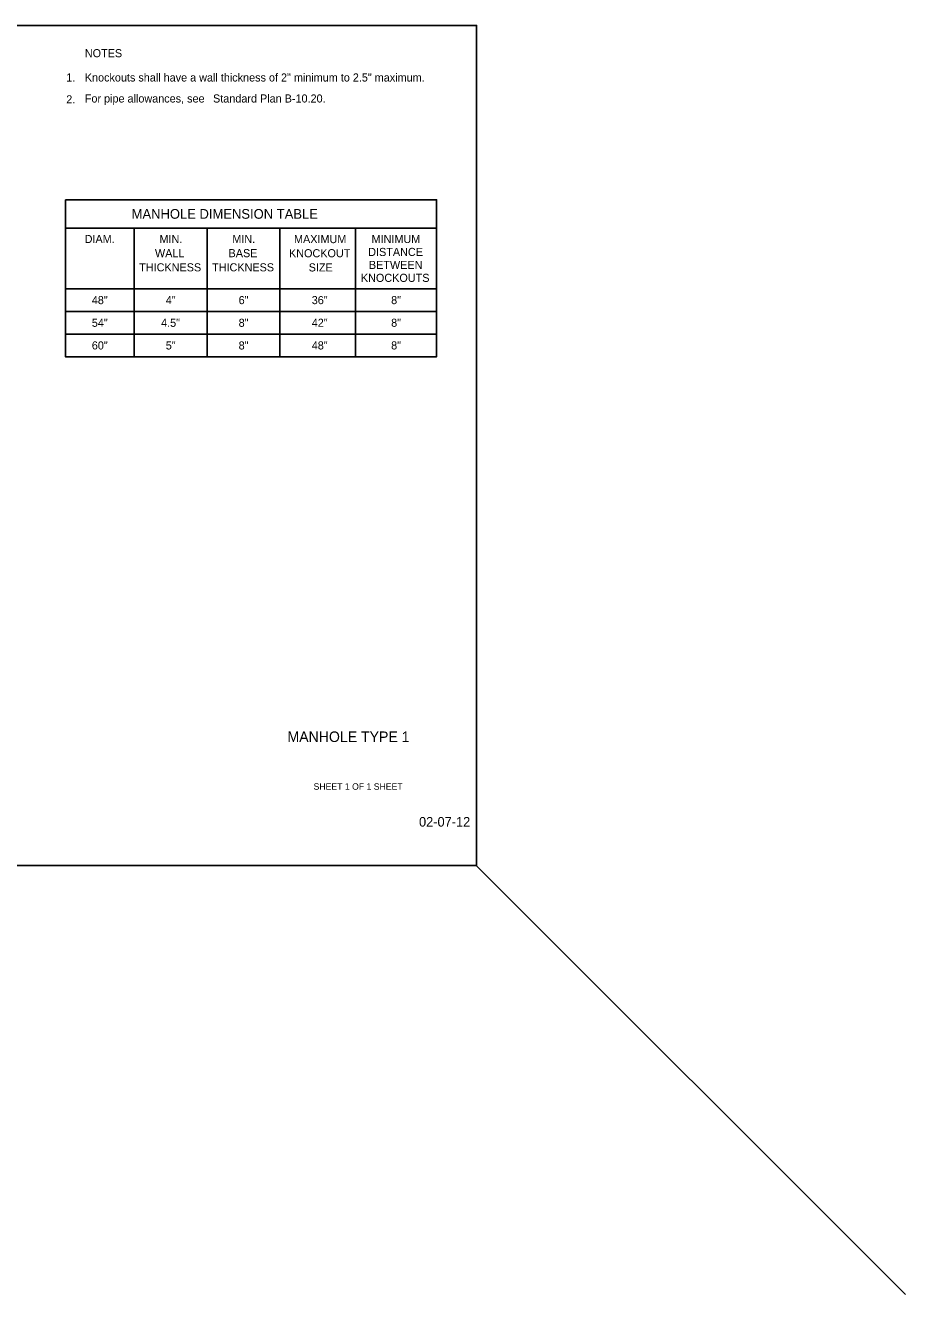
# Model space of a CAD drawing. Extents: x 99862 to 104211, y 98939 to 102076.
# Drawn here: x 102036 to 104211, y 98939 to 102076 of the extents above; entities that cross this region are included whole.
import ezdxf

# ---------------------------------------------------------------- set-up
doc = ezdxf.new("R2010")
doc.units = 0
for name, color, linetype in [('Level 1', 7, 'Continuous'), ('Level 19', 7, 'Continuous'), ('Level 20', 7, 'Continuous'), ('Level 40', 7, 'Continuous'), ('Level 60', 7, 'Continuous'), ('Level 62', 7, 'Continuous')]:
    doc.layers.add(name, color=color, linetype=linetype)

msp = doc.modelspace()

# ---------------------------------------------------------------- linework, layer by layer
at = {"layer": 'Level 1'}
msp.add_line((103150, 100000), (104210.7, 98939.3), dxfattribs=at)
msp.add_lwpolyline([(99862, 99999.5), (103151, 99999.5), (103151, 102075.5), (99862, 102075.5)], close=True, dxfattribs=at)
at = {"layer": 'Level 19'}
for p, q in [((102305.2, 101574.7), (102305.2, 101256.7)), ((102485.2, 101574.7), (102485.2, 101256.7)), ((102665.2, 101574.7), (102665.2, 101256.7)), ((102851.9, 101574.7), (102851.9, 101256.7))]:
    msp.add_line(p, q, dxfattribs=at)
at = {"layer": 'Level 40'}
for p, q in [((103051.9, 101574.7), (102135.2, 101574.7)), ((102135.2, 101424.7), (103051.9, 101424.7)), ((102135.2, 101368.7), (103051.9, 101368.7)), ((102135.2, 101312.7), (103051.9, 101312.7))]:
    msp.add_line(p, q, dxfattribs=at)
msp.add_lwpolyline([(102135.2, 101644.7), (103051.9, 101644.7), (103051.9, 101256.7), (102135.2, 101256.7)], close=True, dxfattribs=at)
at = {"layer": 'Level 60'}
msp.add_line((103151, 102075.5), (103151, 102075.5), dxfattribs=at)

# ---------------------------------------------------------------- texts
at = {"layer": 'Level 1'}
msp.add_text('02-07-12', height=23.62, dxfattribs=at).set_placement((103008.7, 100095.8))
at = {"layer": 'Level 19'}
msp.add_text('MANHOLE DIMENSION TABLE', height=24, dxfattribs=at).set_placement((102298.8, 101597.7))
at = {"layer": 'Level 20'}
for s, p in [('NOTES', (102183.1, 101996.8)), ('1.', (102137.2, 101936.8)), ('Knockouts shall have a wall thickness of 2" minimum to 2.5" maximum.', (102183.1, 101936.8)), ('2.', (102137.2, 101882.8)), ('For pipe allowances, see ', (102183.1, 101884.9)), ('Standard Plan B-10.20.', (102499.9, 101884.9)), ('DIAM.', (102182.7, 101537.7)), ('MIN.', (102367.5, 101537.7)), ('MIN.', (102547.5, 101537.7)), ('MAXIMUM', (102699.9, 101537.5)), ('MINIMUM ', (102891.5, 101537.7)), ('WALL', (102356.4, 101502.7)), ('BASE', (102538.2, 101502.7)), ('KNOCKOUT', (102687.5, 101502.5)), ('DISTANCE', (102883.2, 101505.7)), ('THICKNESS', (102317.5, 101467.7)), ('THICKNESS', (102497.5, 101467.7)), ('SIZE', (102736.1, 101467.5)), ('BETWEEN', (102884.9, 101473.7)), ('KNOCKOUTS', (102865.1, 101441.7)), ('48"', (102200.4, 101386.7)), ('4"', (102383.1, 101386.7)), ('6"', (102563.1, 101386.7)), ('36"', (102743.7, 101386.7)), ('8"', (102939.8, 101386.7)), ('54"', (102200.4, 101330.7)), ('4.5"', (102371.5, 101330.7)), ('8"', (102563.1, 101330.7)), ('42"', (102743.7, 101330.7)), ('8"', (102939.8, 101330.7)), ('60"', (102200.4, 101274.7)), ('5"', (102383.1, 101274.7)), ('8"', (102563.1, 101274.7)), ('48"', (102743.7, 101274.7)), ('8"', (102939.8, 101274.7))]:
    msp.add_text(s, height=20, dxfattribs=at).set_placement(p)
at = {"layer": 'Level 62'}
for s, height, p in [('MANHOLE TYPE 1', 26, (102683.8, 100304.8)), ('SHEET 1 OF 1 SHEET', 16, (102748.2, 100186.8))]:
    msp.add_text(s, height=height, dxfattribs=at).set_placement(p)

doc.saveas('drawing.dxf')
